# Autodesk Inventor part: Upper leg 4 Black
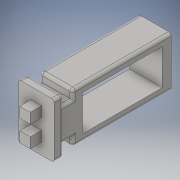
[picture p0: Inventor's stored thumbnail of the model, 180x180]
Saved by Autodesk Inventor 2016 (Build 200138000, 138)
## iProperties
Created: 2015-09
Part Number: Upper leg 4 Black
Material: Generic
Document SubType Name: Modeling
Designer: ChombaW
Density: 1 g/cm^3
Appearance: Default
Author: ChombaW
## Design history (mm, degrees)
sketch "Sketch1"
  geometry: L1 (9.982, 15.24)-(-9.982, 15.24); L2 (-9.982, 15.24)-(-9.982, -15.24); L3 (-9.982, -15.24)-(9.982, -15.24); L4 (9.982, -15.24)-(9.982, 15.24); L5 (9.982, 15.24)-(-9.982, -15.24); L6 (-9.982, 15.24)-(9.982, -15.24); 1 further point
  constraints: 12 end point, 2 midpoint, 2 parallel, 1 horizontal, 1 perpendicular
  dimensions: "d0" = 19.9644 distance of L3.end L2.end; "d1" = 30.48 distance of L2.end L1.end
extrude "Extrusion1" new body sketch "Sketch1" distance "d2" = 5.08; taper "d3" = 0 deg
sketch "Sketch2"
  geometry: L1 (2.921, 3.048)-(-2.921, 3.048); L2 (-2.921, 3.048)-(-2.921, 8.89); L3 (-2.921, 8.89)-(2.921, 8.89); L4 (2.921, 8.89)-(2.921, 3.048); L5 (2.921, 3.048)-(-2.921, 8.89); L6 (-2.921, 3.048)-(2.921, 8.89); L7 (2.921, -8.89)-(-2.921, -8.89); L8 (-2.921, -8.89)-(-2.921, -3.048); L9 (-2.921, -3.048)-(2.921, -3.048); L10 (2.921, -3.048)-(2.921, -8.89); L11 (2.921, -8.89)-(-2.921, -3.048); L12 (-2.921, -8.89)-(2.921, -3.048); L13 (-9.982, -15.24)-(9.982, -15.24) reference; 3 further points
  constraints: 24 end point, 4 midpoint, 4 parallel, 2 horizontal, 2 perpendicular
  dimensions: "d4" = 5.842 distance of L2.end L3.end; "d5" = 5.842 distance of L1.end L2.end; "d6" = 5.842 distance of L8.end L9.end; "d7" = 5.842 distance of L7.end L8.end; "d8" = 6.096 distance of L9.end L1.start; "d9" = 6.35 distance from line of L13 L7.start
extrude "Extrusion2" join sketch "Sketch2" distance "d10" = 6.35; taper "d11" = 0 deg
sketch "Sketch3"
  geometry: L1 (9.144, 9.144)-(-9.144, 9.144); L2 (-9.144, 9.144)-(-9.144, -9.144); L3 (-9.144, -9.144)-(9.144, -9.144); L4 (9.144, -9.144)-(9.144, 9.144); L5 (9.144, 9.144)-(-9.144, -9.144); L6 (-9.144, 9.144)-(9.144, -9.144); 1 further point
  constraints: 12 end point, 2 midpoint, 2 parallel, 1 horizontal, 1 perpendicular
  dimensions: "d12" = 18.288 distance of L3.end L2.end; "d13" = 18.288 distance of L2.end L1.end
extrude "Extrusion3" join sketch "Sketch3" distance "d14" = 6.096; taper "d15" = 0 deg
sketch "Sketch4"
  geometry: L1 (9.144, 13.97)-(-9.144, 13.97); L2 (-9.144, 13.97)-(-9.144, -13.97); L3 (-9.144, -13.97)-(9.144, -13.97); L4 (9.144, -13.97)-(9.144, 13.97); L5 (9.144, 13.97)-(-9.144, -13.97); L6 (-9.144, 13.97)-(9.144, -13.97); 1 further point
  constraints: 12 end point, 2 midpoint, 2 parallel, 1 horizontal, 1 perpendicular
  dimensions: "d16" = 18.288 distance of L3.end L2.end; "d17" = 27.94 distance of L2.end L1.end
extrude "Extrusion4" join sketch "Sketch4" distance "d18" = 55.3212; taper "d19" = 0 deg
sketch "Sketch5"
  geometry: L1 (-56.337, 19.152)-(-11.659, 19.152); L2 (-11.659, 19.152)-(-11.659, -0.864); L3 (-11.659, -0.864)-(-56.337, -0.864); L4 (-56.337, -0.864)-(-56.337, 19.152); L5 (-56.337, 19.152)-(-11.659, -0.864); L6 (-11.659, 19.152)-(-56.337, -0.864); L7 (-6.096, -4.826)-(-61.417, -4.826) reference; L8 (-61.417, -4.826)-(-61.417, 23.114) reference; 2 further points
  constraints: 12 end point, 2 midpoint, 2 parallel, 1 horizontal, 1 perpendicular
  dimensions: "d20" = 44.6786 distance of L2.end L3.end; "d21" = 20.0152 distance of L1.end L2.end; "d22" = 3.9624 distance from line of L7 L2.end; "d23" = 5.08 distance from line of L8 L3.end
extrude "Extrusion5" cut sketch "Sketch5" distance "d24" = 18.288; taper "d25" = 0 deg
fillet "Fillet1" dims "d60" = 1.5875
fillet "Fillet2" dims "d61" = 1.5875
fillet "Fillet3" dims "d62" = 1.5875
fillet "Fillet4" dims "d63" = 1.5875
fillet "Fillet5" dims "d64" = 1.5875
fillet "Fillet6" dims "d65" = 1.5875
fillet "Fillet7" dims "d66" = 1.5875
fillet "Fillet8" dims "d67" = 1.5875
body "Solid1"
